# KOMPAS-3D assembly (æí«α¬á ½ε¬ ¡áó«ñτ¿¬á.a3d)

Referenced files in D:\МОДЕЛЬ ТАНКА Т90\ДЕТАЛИ\БАШНЯ\башня сварная\: люк наводчика.m3d, ось люка наводчика.m3d, люк наводчика1.m3d
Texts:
  Сборка люк наводчика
